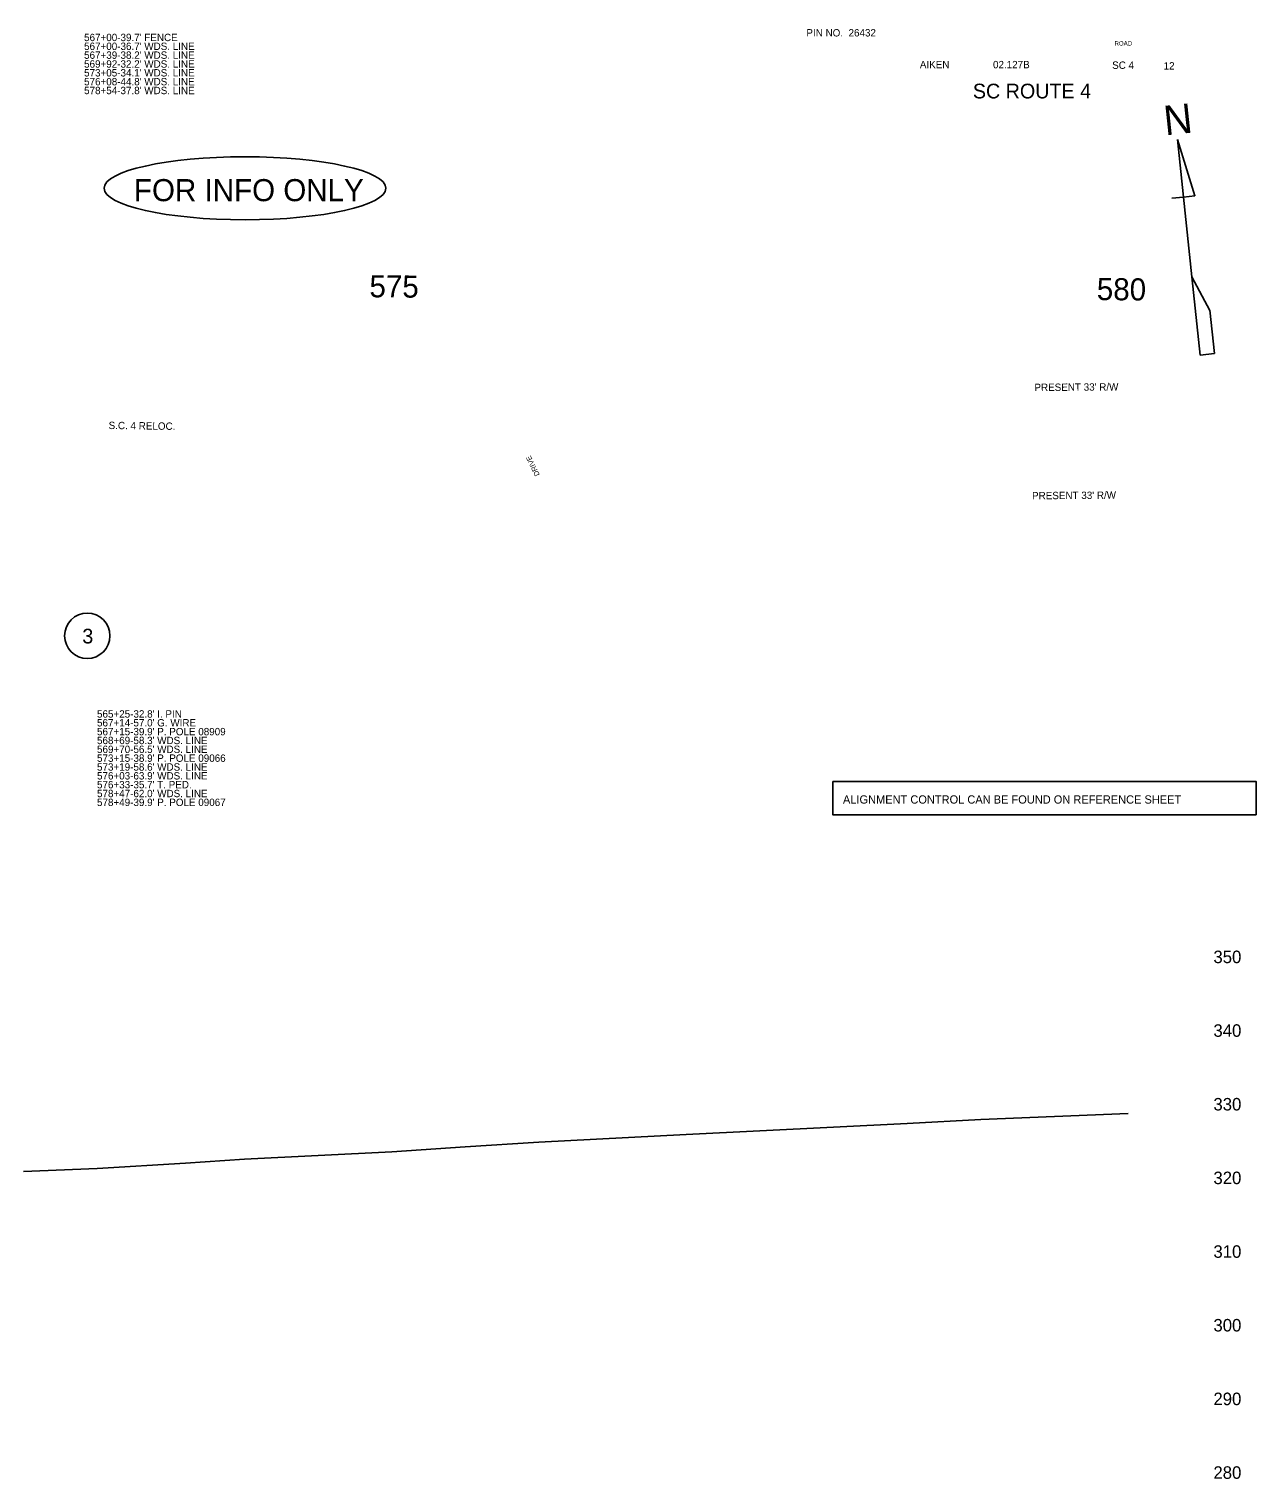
# Model space of a CAD drawing. Extents: x 48556 to 51363, y 45290 to 53458.
# Drawn here: x 49942 to 50775, y 52474 to 53458 of the extents above; entities that cross this region are included whole.
import ezdxf

# ---------------------------------------------------------------- set-up
doc = ezdxf.new("R2010")
doc.units = 0
for name, color, linetype in [('Level 1', 7, 'Continuous'), ('Level 12', 7, 'Continuous'), ('Level 19', 7, 'Continuous'), ('Level 2', 7, 'Continuous'), ('Level 24', 7, 'Continuous'), ('Level 25', 7, 'Continuous'), ('Level 39', 7, 'Continuous'), ('Level 40', 7, 'Continuous'), ('Level 42', 7, 'Continuous'), ('Level 8', 7, 'Continuous')]:
    doc.layers.add(name, color=color, linetype=linetype)

msp = doc.modelspace()

# ---------------------------------------------------------------- linework, layer by layer
at = {"layer": 'Level 12'}
msp.add_circle((49981.24, 53046.16), 15.42, dxfattribs=at)
at = {"layer": 'Level 19'}
msp.add_ellipse((50088.33, 53349.88), major_axis=(95.67, 0), ratio=0.223378, dxfattribs=at)
at = {"layer": 'Level 2'}
for p, q in [((50733.26, 53344.72), (50721.36, 53382.89)), ((50721.36, 53382.89), (50721.36, 53382.89)), ((50721.36, 53382.89), (50725.46, 53343.9)), ((50717.66, 53343.08), (50725.46, 53343.9)), ((50725.46, 53343.9), (50733.26, 53344.72)), ((50731.15, 53289.8), (50725.46, 53343.9)), ((50733.26, 53344.72), (50733.21, 53345.18)), ((50743.4, 53266.95), (50731.15, 53289.8)), ((50731.15, 53289.8), (50736.73, 53236.69)), ((50746.47, 53237.71), (50743.37, 53267.22)), ((50743.37, 53267.22), (50743.4, 53266.95)), ((50736.73, 53236.69), (50746.47, 53237.71))]:
    msp.add_line(p, q, dxfattribs=at)
at = {"layer": 'Level 25'}
msp.add_lwpolyline([(50487.39, 52947.35), (50774.72, 52947.35), (50774.72, 52924.63), (50487.39, 52924.63)], close=True, dxfattribs=at)
at = {"layer": 'Level 40'}
msp.add_lwpolyline([(49937.91, 52682.47), (49987.91, 52684.55), (49987.96, 52684.55), (50047.95, 52688.3), (50087.91, 52690.8), (50137.91, 52693.38), (50187.91, 52695.95), (50237.91, 52699.18), (50287.88, 52702.4), (50387.94, 52707.65), (50437.91, 52710.1), (50487.91, 52712.55), (50537.91, 52715.18), (50587.91, 52717.8), (50637.91, 52719.9), (50687.9, 52722)], dxfattribs=at)

# ---------------------------------------------------------------- texts
at = {"layer": 'Level 1'}
for p in [(50624.31, 53212.22), (50622.69, 53138.74)]:
    msp.add_text("PRESENT 33' R/W", height=5, rotation=0.40349, dxfattribs=at).set_placement(p)
at = {"layer": 'Level 12'}
msp.add_text('3', height=10, dxfattribs=at).set_placement((49977.87, 53040.92))
at = {"layer": 'Level 19'}
msp.add_text('FOR INFO ONLY', height=15, dxfattribs=at).set_placement((50012.93, 53341.1))
for s, p in [('575', (50172.76, 53275.91)), ('580', (50666.58, 53274))]:
    msp.add_text(s, height=15, rotation=359.49443, dxfattribs=at).set_placement(p)
at = {"layer": 'Level 2'}
msp.add_text('N', height=20, rotation=6, dxfattribs=at).set_placement((50713.13, 53385.75))
at = {"layer": 'Level 24'}
for s, height, p in [("567+00-39.7' FENCE", 5, (49979.08, 53449.75)), ('PIN NO.  26432', 5, (50469.47, 53452.91)), ('ROAD', 3, (50678.66, 53446.73)), ("567+00-36.7' WDS. LINE", 5, (49979.08, 53443.75)), ("567+39-38.2' WDS. LINE", 5, (49979.08, 53437.75)), ("569+92-32.2' WDS. LINE", 5, (49979.08, 53431.75)), ("573+05-34.1' WDS. LINE", 5, (49979.08, 53425.75)), ('AIKEN', 5, (50546.51, 53431.32)), ('02.127B', 5, (50596.16, 53431.32)), ('SC 4', 5, (50677.06, 53430.93)), ('12', 5, (50711.97, 53430.45)), ("576+08-44.8' WDS. LINE", 5, (49979.08, 53419.75)), ('SC ROUTE 4', 10, (50582.48, 53410.85)), ("578+54-37.8' WDS. LINE", 5, (49979.08, 53413.75)), ("565+25-32.8' I. PIN", 5, (49987.86, 52990.6)), ("567+14-57.0' G. WIRE", 5, (49987.86, 52984.6)), ("567+15-39.9' P. POLE 08909", 5, (49987.86, 52978.6)), ("568+69-58.3' WDS. LINE", 5, (49987.86, 52972.6)), ("569+70-56.5' WDS. LINE", 5, (49987.86, 52966.6)), ("573+15-38.9' P. POLE 09066", 5, (49987.86, 52960.6)), ("573+19-58.6' WDS. LINE", 5, (49987.86, 52954.6)), ("576+03-63.9' WDS. LINE", 5, (49987.86, 52948.6)), ("576+33-35.7' T. PED.", 5, (49987.86, 52942.6)), ("578+47-62.0' WDS. LINE", 5, (49987.86, 52936.6)), ("578+49-39.9' P. POLE 09067", 5, (49987.86, 52930.6))]:
    msp.add_text(s, height=height, dxfattribs=at).set_placement(p)
at = {"layer": 'Level 25'}
msp.add_text('ALIGNMENT CONTROL CAN BE FOUND ON REFERENCE SHEET', height=5.6, dxfattribs=at).set_placement((50494.29, 52932.24))
at = {"layer": 'Level 39'}
msp.add_text('S.C. 4 RELOC.', height=5, rotation=359.22455, dxfattribs=at).set_placement((49995.7, 53186.47))
at = {"layer": 'Level 42'}
for s, p in [('350', (50745.8, 52823.95)), ('340', (50745.8, 52773.95)), ('330', (50745.8, 52723.95)), ('320', (50745.8, 52673.95)), ('310', (50745.8, 52623.95)), ('300', (50745.8, 52573.95)), ('290', (50745.8, 52523.95)), ('280', (50745.8, 52473.95))]:
    msp.add_text(s, height=8.5, dxfattribs=at).set_placement(p)
at = {"layer": 'Level 8'}
msp.add_text('DRIVE', height=3.5, rotation=115.73869, dxfattribs=at).set_placement((50288.5, 53155.49))

doc.saveas('drawing.dxf')
